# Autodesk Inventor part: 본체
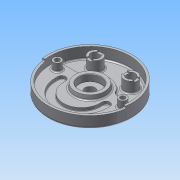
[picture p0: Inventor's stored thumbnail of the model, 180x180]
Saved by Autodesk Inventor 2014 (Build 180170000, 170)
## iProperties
Created: 2015-06
Part Number: 본체
Material: 알루미늄 6061
Document SubType Name: Modeling
Designer: Administrator
Density: 2.71 g/cm^3
Appearance: 알루미늄 - 평지
Mass: 1070.9 g
Surface Area: 1043.54 cm^2
Volume: 395.165 cm^3
Author: Administrator
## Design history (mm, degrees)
sketch "스케치1"
  geometry: C1 r 95 at (0, 0); 1 further point
  constraints: 1 centre point, 1 coincident
  dimensions: "d0" = 190 diameter of C1
extrude "돌출1" new body sketch "스케치1" distance "d1" = 32; taper "d2" = 0 deg
sketch "스케치2"
  geometry: C1 r 95 at (0, 0) reference; C2 r 90 at (0, 0)
  constraints: 1 centre point, 1 coincident
  dimensions: "d3" = 180 diameter of C2
extrude "돌출2" cut sketch "스케치2" distance "d4" = 18; taper "d5" = 0 deg
sketch "스케치3"
  geometry: C1 r 90 at (0, 0) reference; C2 r 35 at (0, 0)
  constraints: 1 centre point, 1 coincident
  dimensions: "d6" = 70 diameter of C2
extrude "돌출3" join sketch "스케치3" distance "d7" = 10; taper "d8" = -10 deg
sketch "스케치4"
  geometry: C1 r 95 at (0, 0) reference; C2 r 26 at (0, 0)
  constraints: 1 centre point, 1 coincident
  dimensions: "d9" = 52 diameter of C2
extrude "돌출4" join sketch "스케치4" distance "d10" = 12; taper "d11" = -15 deg
sketch "스케치5"
  geometry: L1 (-88.566, 16)-(88.566, 16); C1 r 35 at (0, 0) reference; A1 r 90 centre (0, 0) between (-88.566, 16) and (88.566, 16) reference; A2 r 42 centre (0, 0) between (38.833, 16) and (-38.833, 16); A3 r 90 centre (0, 0) between (88.566, 16) and (-88.566, 16)
  constraints: 6 point on circle, 2 centre point, 2 concentric, 2 end point, 2 point on line, 1 coincident, 1 horizontal
  dimensions: "d12" = 84 diameter of A2; "d13" = 16 distance from line of C1.centre L1
extrude "돌출5" cut sketch "스케치5" distance "d14" = 7; taper "d15" = 0 deg
fillet "모깎기1" dims "d16" = 10
sketch "스케치6"
  geometry: C1 r 15 at (-40, 52); C2 r 15 at (40, 52); A1 r 90 centre (0, 0) between (85.114, 29.25) and (-85.114, 29.25) reference
  constraints: 2 centre point, 1 equal radius
  dimensions: "d17" = 30 diameter of C1; "d18" = 52 vertical distance of A1.centre C1.centre; "d19" = 52 vertical distance of A1.centre C2.centre; "d20" = 80 distance of C2.centre C1.centre; "d21" = 40 horizontal distance of A1.centre C1.centre
extrude "돌출6" join sketch "스케치6" distance "d22" = 25; taper "d23" = 0 deg
hole "구멍1" diameter "d26" = 20; stored, may be unused: countersink angle "d30" = 90 deg, drill point angle "d32" = 118 deg; dims "d24" = 10, "d25" = 10, "d27" = 6, "d28" = 4, "d29" = 2, "d31" = 8
hole "구멍2" diameter "d35" = 20; stored, may be unused: countersink angle "d39" = 90 deg, drill point angle "d41" = 118 deg; dims "d33" = 10, "d34" = 10, "d36" = 6, "d37" = 4, "d38" = 2, "d40" = 8
sketch "스케치8"
  geometry: L1 (-6, 20.083)-(6, 20.083); L2 (6, 20.083)-(6, -20.083); L3 (6, -20.083)-(-6, -20.083); L4 (-6, -20.083)-(-6, 20.083); L5 (-6, 20.083)-(6, -20.083); L6 (6, 20.083)-(-6, -20.083); L7 (56.142, 6)-(103.858, 6); L8 (103.858, 6)-(103.858, -6); L9 (103.858, -6)-(56.142, -6); L10 (56.142, -6)-(56.142, 6); L11 (56.142, 6)-(103.858, -6); L12 (103.858, 6)-(56.142, -6); C1 r 15 at (0, 0) reference; C2 r 15 at (80, 0) reference; 1 further point
  constraints: 24 end point, 4 midpoint, 4 parallel, 2 horizontal, 2 perpendicular
  dimensions: "d42" = 12 distance of L1.start L1.end; "d43" = 12 distance of L7.end L8.end; "d44" = 40.16666 distance of L1.end L2.end; "d45" = 47.71654 distance of L7.start L7.end
extrude "돌출7" cut sketch "스케치8" distance "d46" = 3; taper "d47" = 0 deg
hole "구멍3" diameter "d50" = 23; stored, may be unused: countersink angle "d54" = 90 deg, drill point angle "d56" = 118 deg; dims "d48" = 10, "d49" = 10, "d51" = 6, "d52" = 50, "d53" = 15, "d55" = 8
sketch "스케치9"
  geometry: L1 (75.657, 16)-(45.033, 16) reference; L2 (-90, 0)-(90, 0); L3 (-90, -19)-(90, -19); L4 (-90, -14)-(90, -14); L5 (0, 0)-(0, -90); L6 (-59, -19)-(-59, -14); L7 (-41, -19)-(-41, -14); L8 (41, -19)-(41, -14); L9 (59, -19)-(59, -14); C1 r 35 at (0, 0) reference; A1 r 90 centre (0, 0) between (-85.114, 29.25) and (85.114, 29.25) reference; A2 r 41 centre (0, -19) between (-41, -19) and (41, -19); A3 r 59 centre (0, -19) between (-59, -19) and (59, -19); A4 r 9 centre (-50, -14) between (-41, -14) and (-59, -14); A5 r 9 centre (50, -14) between (59, -14) and (41, -14)
  constraints: 16 end point, 11 point on circle, 9 point on line, 8 tangent, 4 centre point, 4 perpendicular, 3 parallel, 1 coincident, 1 midpoint
  dimensions: "d57" = 180 distance of L2.start L2.end; "d58" = 19 distance between parallel lines of L3 L2; "d59" = 5 distance between parallel lines of L3 L4; "d62" = 59 radius of A3; "d63" = 41 radius of A2
extrude "돌출8" cut sketch "스케치9" distance "d64" = 7; taper "d65" = 0 deg
sketch "스케치10"
  geometry: L1 (-95, 0)-(90, 0); L2 (-89.124, -12.526)-(-94.075, -13.221); L3 (89.124, -12.526)-(94.075, -13.221); A1 r 90 centre (0, 0) between (90, 0) and (89.124, -12.526) reference; A2 r 95 centre (0, 0) between (-95, 0) and (-94.075, -13.221) reference; A3 r 90 centre (0, 0) between (-89.124, -12.526) and (89.124, -12.526); A4 r 95 centre (0, 0) between (-94.075, -13.221) and (94.075, -13.221)
  constraints: 10 point on circle, 6 end point, 2 centre point, 2 concentric, 1 horizontal
  dimensions: "d66" = 185 distance of L1.start L1.end; "d67" = 8 deg angle of L2 L1; "d68" = 8 deg angle of L3 L1; "d69" = 0 distance from line of A2.centre L3; "d70" = 0 distance from line of A2.centre L2
extrude "돌출9" cut sketch "스케치10" distance "d71" = 5; taper "d72" = 0 deg
sketch "스케치11"
  geometry: C1 r 35 at (0, 0) reference; C2 r 9 at (-74, 0); C3 r 9 at (74, 0); A1 r 90 centre (0, 0) between (-85.114, 29.25) and (85.114, 29.25) reference; A2 r 74 centre (0, 0) between (-74, 0) and (74, 0)
  constraints: 3 centre point, 2 horizontal alignment, 2 point on circle, 1 coincident
  dimensions: "d73" = 148 diameter of A2; "d74" = 18 diameter of C2; "d75" = 18 diameter of C3
extrude "돌출10" join sketch "스케치11" distance "d76" = 18; taper "d77" = 0 deg
sketch "스케치12"
  geometry: C1 r 9 at (74, 0) reference; C2 r 9 at (-74, 0) reference; 2 further points
  constraints: 2 coincident
hole "구멍4" sketch "스케치12" at (-74, 0), (74, 0) diameter "d78" = 11; stored, may be unused: countersink angle "d82" = 90 deg, drill point angle "d84" = 118 deg; dims "d79" = 6, "d80" = 18, "d81" = 11, "d83" = 8
sketch "스케치13"
  geometry: C1 r 95 at (0, 0) reference; C2 r 68 at (0, 0)
  constraints: 1 centre point, 1 coincident, 1 other
  dimensions: "d85" = 136 diameter of C2
feature "엠보싱1" sketch "스케치13" dims "d1" = 32, "d86" = 0.5, "d87" = 0
fillet "모깎기2" dims "d88" = 3
fillet "모깎기3" dims "d89" = 3
fillet "모깎기4" dims "d90" = 5
fillet "모깎기5" dims "d91" = 3
fillet "모깎기6" dims "d92" = 0.3
chamfer "모따기1" distance "d93" = 1; stored, may be unused: second distance "d94" = 2, angle "d95" = 45 deg
fillet "모깎기7" dims "d96" = 3
fillet "모깎기8" dims "d97" = 3
fillet "모깎기9" dims "d98" = 1
fillet "모깎기10" dims "d99" = 3
node "솔리드1"
other parameters: "d60" = 82, "d61" = 118
